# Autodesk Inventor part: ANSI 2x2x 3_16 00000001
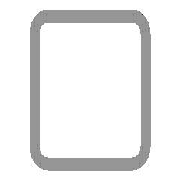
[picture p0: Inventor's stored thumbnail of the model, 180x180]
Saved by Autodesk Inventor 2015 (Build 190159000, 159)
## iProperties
IsCustomPart: 1
Created: 2007-02
Part Number: ANSI 2x2x 3_16 00000001
Material: Steel
Document SubType Name: Modeling
Standard: AISC
Designer: Autodesk, Inc.
Size Designation: 2x2x3/16
Stock Number: 2x2x 3/16
Density: 7.85 g/cm^3
Description: Tube
Standards Organization: ANSI
Language: en-US
Categories: <MemberInstance><Categories><Category DisplayName="Structural Shapes" InternalName="089c4875-fa83-4c05-b084-43b9cc11f5ed" Mnemonic="GRDR"><CategoryParameter Dis
Mass: 3346.04 g
Surface Area: 1806.39 cm^2
Volume: 426.248 cm^3
Appearance: Steel
_FrameMemberDoc: Frame Member File
_Version: 15.0.0
_CCFamilyMember: 1
_CCFamilyDisplayName: ANSI AISC (Square) - Tube
G_L: 20.500 in
G_W: 2.000 in
G_H: 2.000 in
+68D46622-7D41-4F1B-95F4-B5CED4C39EB1+CUTDETAIL1: Cut
+615A4260-BFBF-472F-B8C1-1B86C782A88A+CUTDETAIL2: Cut
Author: Autodesk, Inc.
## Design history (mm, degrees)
node "Start plane"
node "End plane"
sketch "Sketch"
  geometry: L1 (-25.4, -15.875)-(-25.4, 15.875); L2 (-15.875, 25.4)-(15.875, 25.4); L3 (25.4, 15.875)-(25.4, -15.875); L4 (15.875, -25.4)-(-15.875, -25.4); L5 (-15.875, 20.637)-(15.875, 20.638); L6 (20.637, 15.875)-(20.637, -15.875); L7 (15.875, -20.637)-(-15.875, -20.638); L8 (-20.637, -15.875)-(-20.637, 15.875); L9 (0, 38.322)-(0, -38.322) reference; L10 (-38.322, 0)-(38.322, 0) reference; A1 r 9.525 centre (-15.875, -15.875) between (-25.4, -15.875) and (-15.875, -25.4); A2 r 9.525 centre (-15.875, 15.875) between (-15.875, 25.4) and (-25.4, 15.875); A3 r 9.525 centre (15.875, 15.875) between (25.4, 15.875) and (15.875, 25.4); A4 r 9.525 centre (15.875, -15.875) between (15.875, -25.4) and (25.4, -15.875); A5 r 4.762 centre (-15.875, 15.875) between (-15.875, 20.637) and (-20.637, 15.875); A6 r 4.762 centre (15.875, 15.875) between (20.637, 15.875) and (15.875, 20.638); A7 r 4.762 centre (15.875, -15.875) between (15.875, -20.637) and (20.637, -15.875); A8 r 4.762 centre (-15.875, -15.875) between (-20.637, -15.875) and (-15.875, -20.638)
  constraints: 16 end point, 16 point on circle, 8 centre point, 8 tangent, 4 parallel, 3 equal radius, 2 perpendicular, 7 other
  dimensions: "d10" = 50.8 distance between parallel lines of L2 L4 (= G_H); "d11" = 50.8 distance between parallel lines of L1 L3 (= G_W); "d12" = 4.7625 distance between parallel lines of L3 L6 (= G_T); "d15" = 25.4 distance between parallel lines of L2 L10 (= 0.5 x d10); "d16" = 25.4 distance between parallel lines of L9 L3 (= 0.5 x d11); "d17" = 9.525 radius of A1 (= G_IR)
extrude "Body" new body sketch "Sketch" stored distance "d3" = 520.7 (= G_L); taper "d4" = 0 deg
node "Driven Length"
  sketch "Sketch3"
    geometry: L1 (0, 0)-(10, 0) reference
    constraints: 2 end point, 1 horizontal
  workplane "Work Plane5"
  sketch "Sketch4"
    geometry: L1 (-2, -6.35)-(12, -6.35) reference; L2 (-2, 514.35)-(12, 514.35) reference
    dimensions: "d19" = 520.7 distance between parallel lines of L1 L2 (derived)
workplane "Work Plane3"
split "Split1"
workplane "Work Plane4"
split "Split2"
body "Solid1"
other parameters: "G_W" = 50.8 [user parameter; used in 1 equation term], "G_H" = 50.8 [user parameter; used in 1 equation term], "G_T" = 4.7625 [user parameter; used in 1 equation term], "G_IR" = 9.525 [user parameter; used in 1 equation term], "G_L" = 520.7 (= d19) [user parameter; used in 1 equation term], "G_OFFSET_START" = 6.35 [user parameter; used in 1 equation term], "G_OFFSET_END" = 6.35 [user parameter; used in 1 equation term], "d13" = -6.35 (= -G_OFFSET_START), "d14" = 514.35 (= G_OFFSET_END + B_L), "B_L" = 508 [user parameter; used in 1 equation term], "d18" = 90 deg
